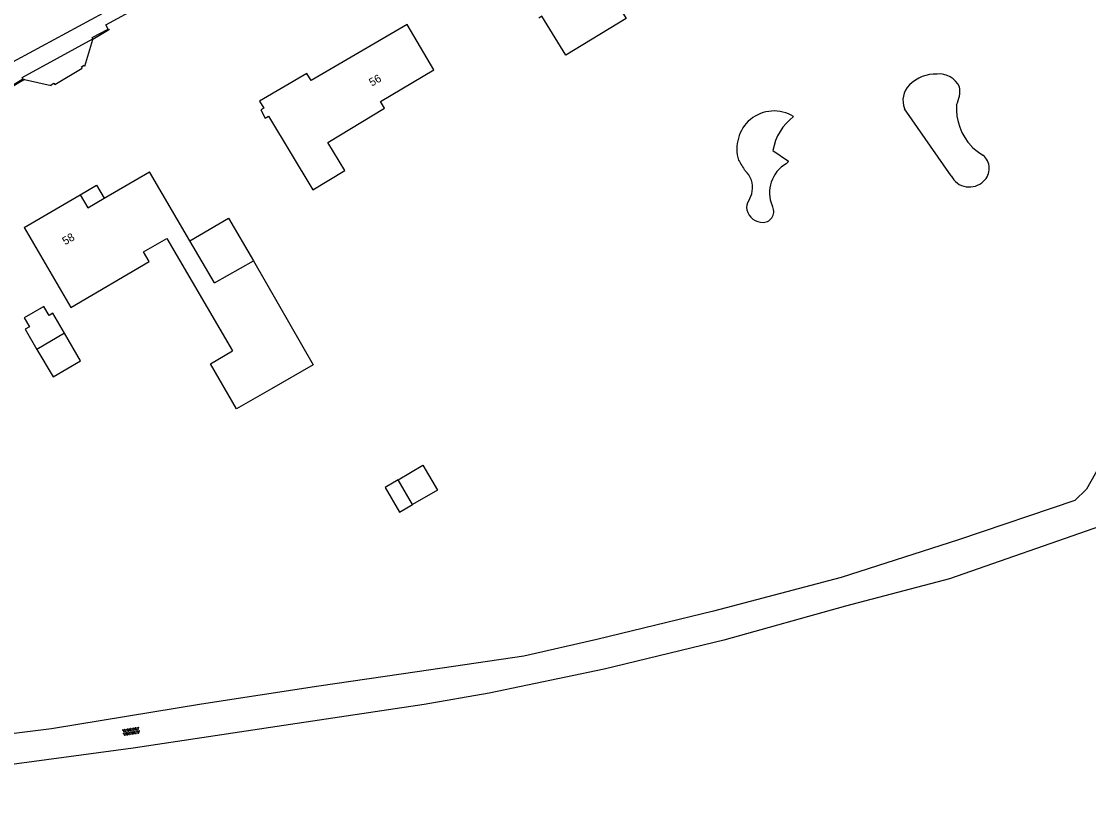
# Model space of a CAD drawing. Extents: x 135999 to 138000, y 396000 to 398501.
# Drawn here: x 136414.4 to 136547.8, y 397514.6 to 397614 of the extents above; entities that cross this region are included whole.
import ezdxf

# ---------------------------------------------------------------- set-up
doc = ezdxf.new("R2010")
doc.units = 0
for name, color, linetype in [('gg-afsc-hekwerk', 7, 'Continuous'), ('gg-anno-huisnummerreeks BGT', 7, 'Continuous'), ('gg-bbg-gedigitaliseerde bebouwing', 7, 'Continuous'), ('gg-bbg-gedigitaliseerde bijgebouw', 7, 'Continuous'), ('gg-bbg-hoofdgebouw', 7, 'Continuous'), ('gg-bbg-luifel en loopbrug', 7, 'Continuous'), ('gg-knt-onverhard', 7, 'Continuous'), ('gg-knt-verharding', 7, 'Continuous'), ('gg-kntw-bovenkant insteek waterloop', 7, 'Continuous'), ('gt-symb-overige verharding', 7, 'Continuous')]:
    doc.layers.add(name, color=color, linetype=linetype)

# ---------------------------------------------------------------- blocks, each defined once
blk = doc.blocks.new('gt0-OVH')
at = {"layer": 'gt-symb-overige verharding'}
for points in [[(-0.97, 0.3), (-0.97, 0.31), (-0.96, 0.32), (-0.97, 0.33), (-0.97, 0.34), (-0.98, 0.35), (-0.99, 0.35), (-1, 0.36), (-1.01, 0.35), (-1.02, 0.35), (-1.03, 0.34), (-1.03, 0.33), (-1.04, 0.32), (-1.03, 0.31), (-1.03, 0.3), (-1.02, 0.29), (-1.01, 0.29), (-1, 0.28), (-0.99, 0.29), (-0.98, 0.29)], [(-0.87, 0.11), (-0.87, 0.12), (-0.86, 0.13), (-0.87, 0.14), (-0.87, 0.15), (-0.88, 0.16), (-0.89, 0.16), (-0.9, 0.16), (-0.91, 0.16), (-0.92, 0.16), (-0.93, 0.15), (-0.93, 0.14), (-0.94, 0.13), (-0.93, 0.12), (-0.93, 0.11), (-0.92, 0.1), (-0.91, 0.09), (-0.9, 0.09), (-0.89, 0.09), (-0.88, 0.1)], [(-0.77, 0.3), (-0.77, 0.31), (-0.76, 0.32), (-0.77, 0.33), (-0.77, 0.34), (-0.78, 0.35), (-0.79, 0.35), (-0.8, 0.36), (-0.81, 0.35), (-0.82, 0.35), (-0.83, 0.34), (-0.83, 0.33), (-0.84, 0.32), (-0.83, 0.31), (-0.83, 0.3), (-0.82, 0.29), (-0.81, 0.29), (-0.8, 0.28), (-0.79, 0.29), (-0.78, 0.29)], [(-0.67, 0.11), (-0.67, 0.12), (-0.66, 0.13), (-0.67, 0.14), (-0.67, 0.15), (-0.68, 0.16), (-0.69, 0.16), (-0.7, 0.16), (-0.71, 0.16), (-0.72, 0.16), (-0.73, 0.15), (-0.73, 0.14), (-0.74, 0.13), (-0.73, 0.12), (-0.73, 0.11), (-0.72, 0.1), (-0.71, 0.09), (-0.7, 0.09), (-0.69, 0.09), (-0.68, 0.1)], [(-0.57, 0.3), (-0.57, 0.31), (-0.56, 0.32), (-0.57, 0.33), (-0.57, 0.34), (-0.58, 0.35), (-0.59, 0.35), (-0.6, 0.36), (-0.61, 0.35), (-0.62, 0.35), (-0.63, 0.34), (-0.63, 0.33), (-0.64, 0.32), (-0.63, 0.31), (-0.63, 0.3), (-0.62, 0.29), (-0.61, 0.29), (-0.6, 0.28), (-0.59, 0.29), (-0.58, 0.29)], [(-0.47, 0.11), (-0.47, 0.12), (-0.46, 0.13), (-0.47, 0.14), (-0.47, 0.15), (-0.48, 0.16), (-0.49, 0.16), (-0.5, 0.16), (-0.51, 0.16), (-0.52, 0.16), (-0.53, 0.15), (-0.53, 0.14), (-0.54, 0.13), (-0.53, 0.12), (-0.53, 0.11), (-0.52, 0.1), (-0.51, 0.09), (-0.5, 0.09), (-0.49, 0.09), (-0.48, 0.1)], [(-0.37, 0.3), (-0.37, 0.31), (-0.36, 0.32), (-0.37, 0.33), (-0.37, 0.34), (-0.38, 0.35), (-0.39, 0.35), (-0.4, 0.36), (-0.41, 0.35), (-0.42, 0.35), (-0.43, 0.34), (-0.43, 0.33), (-0.44, 0.32), (-0.43, 0.31), (-0.43, 0.3), (-0.42, 0.29), (-0.41, 0.29), (-0.4, 0.28), (-0.39, 0.29), (-0.38, 0.29)], [(-0.27, 0.11), (-0.27, 0.12), (-0.26, 0.13), (-0.27, 0.14), (-0.27, 0.15), (-0.28, 0.16), (-0.29, 0.16), (-0.3, 0.16), (-0.31, 0.16), (-0.32, 0.16), (-0.33, 0.15), (-0.33, 0.14), (-0.34, 0.13), (-0.33, 0.12), (-0.33, 0.11), (-0.32, 0.1), (-0.31, 0.09), (-0.3, 0.09), (-0.29, 0.09), (-0.28, 0.1)], [(-0.17, 0.3), (-0.17, 0.31), (-0.16, 0.32), (-0.17, 0.33), (-0.17, 0.34), (-0.18, 0.35), (-0.19, 0.35), (-0.2, 0.36), (-0.21, 0.35), (-0.22, 0.35), (-0.23, 0.34), (-0.23, 0.33), (-0.24, 0.32), (-0.23, 0.31), (-0.23, 0.3), (-0.22, 0.29), (-0.21, 0.29), (-0.2, 0.28), (-0.19, 0.29), (-0.18, 0.29)], [(-0.07, 0.11), (-0.07, 0.12), (-0.06, 0.13), (-0.07, 0.14), (-0.07, 0.15), (-0.08, 0.16), (-0.09, 0.16), (-0.1, 0.16), (-0.11, 0.16), (-0.12, 0.16), (-0.13, 0.15), (-0.13, 0.14), (-0.14, 0.13), (-0.13, 0.12), (-0.13, 0.11), (-0.12, 0.1), (-0.11, 0.09), (-0.1, 0.09), (-0.09, 0.09), (-0.08, 0.1)], [(0.03, 0.3), (0.03, 0.31), (0.04, 0.32), (0.03, 0.33), (0.03, 0.34), (0.02, 0.35), (0.01, 0.35), (0, 0.36), (-0.01, 0.35), (-0.02, 0.35), (-0.03, 0.34), (-0.03, 0.33), (-0.04, 0.32), (-0.03, 0.31), (-0.03, 0.3), (-0.02, 0.29), (-0.01, 0.29), (0, 0.28), (0.01, 0.29), (0.02, 0.29)], [(0.13, 0.11), (0.13, 0.12), (0.14, 0.13), (0.13, 0.14), (0.13, 0.15), (0.12, 0.16), (0.11, 0.16), (0.1, 0.16), (0.09, 0.16), (0.08, 0.16), (0.07, 0.15), (0.07, 0.14), (0.06, 0.13), (0.07, 0.12), (0.07, 0.11), (0.08, 0.1), (0.09, 0.09), (0.1, 0.09), (0.11, 0.09), (0.12, 0.1)], [(0.23, 0.3), (0.23, 0.31), (0.24, 0.32), (0.23, 0.33), (0.23, 0.34), (0.22, 0.35), (0.21, 0.35), (0.2, 0.36), (0.19, 0.35), (0.18, 0.35), (0.17, 0.34), (0.17, 0.33), (0.16, 0.32), (0.17, 0.31), (0.17, 0.3), (0.18, 0.29), (0.19, 0.29), (0.2, 0.28), (0.21, 0.29), (0.22, 0.29)], [(0.33, 0.11), (0.33, 0.12), (0.34, 0.13), (0.33, 0.14), (0.33, 0.15), (0.32, 0.16), (0.31, 0.16), (0.3, 0.16), (0.29, 0.16), (0.28, 0.16), (0.27, 0.15), (0.27, 0.14), (0.26, 0.13), (0.27, 0.12), (0.27, 0.11), (0.28, 0.1), (0.29, 0.09), (0.3, 0.09), (0.31, 0.09), (0.32, 0.1)], [(0.43, 0.3), (0.43, 0.31), (0.44, 0.32), (0.43, 0.33), (0.43, 0.34), (0.42, 0.35), (0.41, 0.35), (0.4, 0.36), (0.39, 0.35), (0.38, 0.35), (0.37, 0.34), (0.37, 0.33), (0.36, 0.32), (0.37, 0.31), (0.37, 0.3), (0.38, 0.29), (0.39, 0.29), (0.4, 0.28), (0.41, 0.29), (0.42, 0.29)], [(0.53, 0.11), (0.53, 0.12), (0.54, 0.13), (0.53, 0.14), (0.53, 0.15), (0.52, 0.16), (0.51, 0.16), (0.5, 0.16), (0.49, 0.16), (0.48, 0.16), (0.47, 0.15), (0.47, 0.14), (0.46, 0.13), (0.47, 0.12), (0.47, 0.11), (0.48, 0.1), (0.49, 0.09), (0.5, 0.09), (0.51, 0.09), (0.52, 0.1)], [(0.63, 0.3), (0.63, 0.31), (0.64, 0.32), (0.63, 0.33), (0.63, 0.34), (0.62, 0.35), (0.61, 0.35), (0.6, 0.36), (0.59, 0.35), (0.58, 0.35), (0.57, 0.34), (0.57, 0.33), (0.56, 0.32), (0.57, 0.31), (0.57, 0.3), (0.58, 0.29), (0.59, 0.29), (0.6, 0.28), (0.61, 0.29), (0.62, 0.29)], [(0.73, 0.11), (0.73, 0.12), (0.74, 0.13), (0.73, 0.14), (0.73, 0.15), (0.72, 0.16), (0.71, 0.16), (0.7, 0.16), (0.69, 0.16), (0.68, 0.16), (0.67, 0.15), (0.67, 0.14), (0.66, 0.13), (0.67, 0.12), (0.67, 0.11), (0.68, 0.1), (0.69, 0.09), (0.7, 0.09), (0.71, 0.09), (0.72, 0.1)], [(0.83, 0.3), (0.83, 0.31), (0.84, 0.32), (0.83, 0.33), (0.83, 0.34), (0.82, 0.35), (0.81, 0.35), (0.8, 0.36), (0.79, 0.35), (0.78, 0.35), (0.77, 0.34), (0.77, 0.33), (0.76, 0.32), (0.77, 0.31), (0.77, 0.3), (0.78, 0.29), (0.79, 0.29), (0.8, 0.28), (0.81, 0.29), (0.82, 0.29)], [(0.93, 0.11), (0.93, 0.12), (0.94, 0.13), (0.93, 0.14), (0.93, 0.15), (0.92, 0.16), (0.91, 0.16), (0.9, 0.16), (0.89, 0.16), (0.88, 0.16), (0.87, 0.15), (0.87, 0.14), (0.86, 0.13), (0.87, 0.12), (0.87, 0.11), (0.88, 0.1), (0.89, 0.09), (0.9, 0.09), (0.91, 0.09), (0.92, 0.1)], [(1.03, 0.3), (1.03, 0.31), (1.04, 0.32), (1.03, 0.33), (1.03, 0.34), (1.02, 0.35), (1.01, 0.35), (1, 0.36), (0.99, 0.35), (0.98, 0.35), (0.97, 0.34), (0.97, 0.33), (0.96, 0.32), (0.97, 0.31), (0.97, 0.3), (0.98, 0.29), (0.99, 0.29), (1, 0.28), (1.01, 0.29), (1.02, 0.29)], [(-0.97, -0.14), (-0.97, -0.13), (-0.96, -0.12), (-0.97, -0.11), (-0.97, -0.1), (-0.98, -0.09), (-0.99, -0.09), (-1, -0.08), (-1.01, -0.09), (-1.02, -0.09), (-1.03, -0.1), (-1.03, -0.11), (-1.04, -0.12), (-1.03, -0.13), (-1.03, -0.14), (-1.02, -0.15), (-1.01, -0.15), (-1, -0.16), (-0.99, -0.15), (-0.98, -0.15)], [(-0.87, -0.33), (-0.87, -0.32), (-0.86, -0.31), (-0.87, -0.3), (-0.87, -0.29), (-0.88, -0.28), (-0.89, -0.28), (-0.9, -0.28), (-0.91, -0.28), (-0.92, -0.28), (-0.93, -0.29), (-0.93, -0.3), (-0.94, -0.31), (-0.93, -0.32), (-0.93, -0.33), (-0.92, -0.34), (-0.91, -0.35), (-0.9, -0.35), (-0.89, -0.35), (-0.88, -0.34)], [(-0.77, -0.14), (-0.77, -0.13), (-0.76, -0.12), (-0.77, -0.11), (-0.77, -0.1), (-0.78, -0.09), (-0.79, -0.09), (-0.8, -0.08), (-0.81, -0.09), (-0.82, -0.09), (-0.83, -0.1), (-0.83, -0.11), (-0.84, -0.12), (-0.83, -0.13), (-0.83, -0.14), (-0.82, -0.15), (-0.81, -0.15), (-0.8, -0.16), (-0.79, -0.15), (-0.78, -0.15)], [(-0.67, -0.33), (-0.67, -0.32), (-0.66, -0.31), (-0.67, -0.3), (-0.67, -0.29), (-0.68, -0.28), (-0.69, -0.28), (-0.7, -0.28), (-0.71, -0.28), (-0.72, -0.28), (-0.73, -0.29), (-0.73, -0.3), (-0.74, -0.31), (-0.73, -0.32), (-0.73, -0.33), (-0.72, -0.34), (-0.71, -0.35), (-0.7, -0.35), (-0.69, -0.35), (-0.68, -0.34)], [(-0.57, -0.14), (-0.57, -0.13), (-0.56, -0.12), (-0.57, -0.11), (-0.57, -0.1), (-0.58, -0.09), (-0.59, -0.09), (-0.6, -0.08), (-0.61, -0.09), (-0.62, -0.09), (-0.63, -0.1), (-0.63, -0.11), (-0.64, -0.12), (-0.63, -0.13), (-0.63, -0.14), (-0.62, -0.15), (-0.61, -0.15), (-0.6, -0.16), (-0.59, -0.15), (-0.58, -0.15)], [(-0.47, -0.33), (-0.47, -0.32), (-0.46, -0.31), (-0.47, -0.3), (-0.47, -0.29), (-0.48, -0.28), (-0.49, -0.28), (-0.5, -0.28), (-0.51, -0.28), (-0.52, -0.28), (-0.53, -0.29), (-0.53, -0.3), (-0.54, -0.31), (-0.53, -0.32), (-0.53, -0.33), (-0.52, -0.34), (-0.51, -0.35), (-0.5, -0.35), (-0.49, -0.35), (-0.48, -0.34)], [(-0.37, -0.14), (-0.37, -0.13), (-0.36, -0.12), (-0.37, -0.11), (-0.37, -0.1), (-0.38, -0.09), (-0.39, -0.09), (-0.4, -0.08), (-0.41, -0.09), (-0.42, -0.09), (-0.43, -0.1), (-0.43, -0.11), (-0.44, -0.12), (-0.43, -0.13), (-0.43, -0.14), (-0.42, -0.15), (-0.41, -0.15), (-0.4, -0.16), (-0.39, -0.15), (-0.38, -0.15)], [(-0.27, -0.33), (-0.27, -0.32), (-0.26, -0.31), (-0.27, -0.3), (-0.27, -0.29), (-0.28, -0.28), (-0.29, -0.28), (-0.3, -0.28), (-0.31, -0.28), (-0.32, -0.28), (-0.33, -0.29), (-0.33, -0.3), (-0.34, -0.31), (-0.33, -0.32), (-0.33, -0.33), (-0.32, -0.34), (-0.31, -0.35), (-0.3, -0.35), (-0.29, -0.35), (-0.28, -0.34)], [(-0.17, -0.14), (-0.17, -0.13), (-0.16, -0.12), (-0.17, -0.11), (-0.17, -0.1), (-0.18, -0.09), (-0.19, -0.09), (-0.2, -0.08), (-0.21, -0.09), (-0.22, -0.09), (-0.23, -0.1), (-0.23, -0.11), (-0.24, -0.12), (-0.23, -0.13), (-0.23, -0.14), (-0.22, -0.15), (-0.21, -0.15), (-0.2, -0.16), (-0.19, -0.15), (-0.18, -0.15)], [(-0.07, -0.33), (-0.07, -0.32), (-0.06, -0.31), (-0.07, -0.3), (-0.07, -0.29), (-0.08, -0.28), (-0.09, -0.28), (-0.1, -0.28), (-0.11, -0.28), (-0.12, -0.28), (-0.13, -0.29), (-0.13, -0.3), (-0.14, -0.31), (-0.13, -0.32), (-0.13, -0.33), (-0.12, -0.34), (-0.11, -0.35), (-0.1, -0.35), (-0.09, -0.35), (-0.08, -0.34)], [(0.03, -0.14), (0.03, -0.13), (0.04, -0.12), (0.03, -0.11), (0.03, -0.1), (0.02, -0.09), (0.01, -0.09), (0, -0.08), (-0.01, -0.09), (-0.02, -0.09), (-0.03, -0.1), (-0.03, -0.11), (-0.04, -0.12), (-0.03, -0.13), (-0.03, -0.14), (-0.02, -0.15), (-0.01, -0.15), (0, -0.16), (0.01, -0.15), (0.02, -0.15)], [(0.13, -0.33), (0.13, -0.32), (0.14, -0.31), (0.13, -0.3), (0.13, -0.29), (0.12, -0.28), (0.11, -0.28), (0.1, -0.28), (0.09, -0.28), (0.08, -0.28), (0.07, -0.29), (0.07, -0.3), (0.06, -0.31), (0.07, -0.32), (0.07, -0.33), (0.08, -0.34), (0.09, -0.35), (0.1, -0.35), (0.11, -0.35), (0.12, -0.34)], [(0.23, -0.14), (0.23, -0.13), (0.24, -0.12), (0.23, -0.11), (0.23, -0.1), (0.22, -0.09), (0.21, -0.09), (0.2, -0.08), (0.19, -0.09), (0.18, -0.09), (0.17, -0.1), (0.17, -0.11), (0.16, -0.12), (0.17, -0.13), (0.17, -0.14), (0.18, -0.15), (0.19, -0.15), (0.2, -0.16), (0.21, -0.15), (0.22, -0.15)], [(0.33, -0.33), (0.33, -0.32), (0.34, -0.31), (0.33, -0.3), (0.33, -0.29), (0.32, -0.28), (0.31, -0.28), (0.3, -0.28), (0.29, -0.28), (0.28, -0.28), (0.27, -0.29), (0.27, -0.3), (0.26, -0.31), (0.27, -0.32), (0.27, -0.33), (0.28, -0.34), (0.29, -0.35), (0.3, -0.35), (0.31, -0.35), (0.32, -0.34)], [(0.43, -0.14), (0.43, -0.13), (0.44, -0.12), (0.43, -0.11), (0.43, -0.1), (0.42, -0.09), (0.41, -0.09), (0.4, -0.08), (0.39, -0.09), (0.38, -0.09), (0.37, -0.1), (0.37, -0.11), (0.36, -0.12), (0.37, -0.13), (0.37, -0.14), (0.38, -0.15), (0.39, -0.15), (0.4, -0.16), (0.41, -0.15), (0.42, -0.15)], [(0.53, -0.33), (0.53, -0.32), (0.54, -0.31), (0.53, -0.3), (0.53, -0.29), (0.52, -0.28), (0.51, -0.28), (0.5, -0.28), (0.49, -0.28), (0.48, -0.28), (0.47, -0.29), (0.47, -0.3), (0.46, -0.31), (0.47, -0.32), (0.47, -0.33), (0.48, -0.34), (0.49, -0.35), (0.5, -0.35), (0.51, -0.35), (0.52, -0.34)], [(0.63, -0.14), (0.63, -0.13), (0.64, -0.12), (0.63, -0.11), (0.63, -0.1), (0.62, -0.09), (0.61, -0.09), (0.6, -0.08), (0.59, -0.09), (0.58, -0.09), (0.57, -0.1), (0.57, -0.11), (0.56, -0.12), (0.57, -0.13), (0.57, -0.14), (0.58, -0.15), (0.59, -0.15), (0.6, -0.16), (0.61, -0.15), (0.62, -0.15)], [(0.73, -0.33), (0.73, -0.32), (0.74, -0.31), (0.73, -0.3), (0.73, -0.29), (0.72, -0.28), (0.71, -0.28), (0.7, -0.28), (0.69, -0.28), (0.68, -0.28), (0.67, -0.29), (0.67, -0.3), (0.66, -0.31), (0.67, -0.32), (0.67, -0.33), (0.68, -0.34), (0.69, -0.35), (0.7, -0.35), (0.71, -0.35), (0.72, -0.34)], [(0.83, -0.14), (0.83, -0.13), (0.84, -0.12), (0.83, -0.11), (0.83, -0.1), (0.82, -0.09), (0.81, -0.09), (0.8, -0.08), (0.79, -0.09), (0.78, -0.09), (0.77, -0.1), (0.77, -0.11), (0.76, -0.12), (0.77, -0.13), (0.77, -0.14), (0.78, -0.15), (0.79, -0.15), (0.8, -0.16), (0.81, -0.15), (0.82, -0.15)], [(0.93, -0.33), (0.93, -0.32), (0.94, -0.31), (0.93, -0.3), (0.93, -0.29), (0.92, -0.28), (0.91, -0.28), (0.9, -0.28), (0.89, -0.28), (0.88, -0.28), (0.87, -0.29), (0.87, -0.3), (0.86, -0.31), (0.87, -0.32), (0.87, -0.33), (0.88, -0.34), (0.89, -0.35), (0.9, -0.35), (0.91, -0.35), (0.92, -0.34)], [(1.03, -0.14), (1.03, -0.13), (1.04, -0.12), (1.03, -0.11), (1.03, -0.1), (1.02, -0.09), (1.01, -0.09), (1, -0.08), (0.99, -0.09), (0.98, -0.09), (0.97, -0.1), (0.97, -0.11), (0.96, -0.12), (0.97, -0.13), (0.97, -0.14), (0.98, -0.15), (0.99, -0.15), (1, -0.16), (1.01, -0.15), (1.02, -0.15)]]:
    blk.add_lwpolyline(points, close=True, dxfattribs=at)

msp = doc.modelspace()

# ---------------------------------------------------------------- linework, layer by layer
at = {"layer": 'gg-afsc-hekwerk'}
for p, q in [((136425.44, 397612.99), (136423.33, 397611.76)), ((136423.33, 397611.76), (136423.35, 397611.81)), ((136414.81, 397606.76), (136376.12, 397584.09)), ((136414.59, 397606.81), (136414.81, 397606.76))]:
    msp.add_line(p, q, dxfattribs=at)
for points in [[(136414.81, 397606.76), (136418.15, 397605.99), (136418.13, 397606.09), (136418.46, 397606.28), (136418.58, 397606.14), (136421.99, 397608.18), (136421.93, 397608.34), (136422.26, 397608.52), (136422.35, 397608.4), (136423.33, 397611.76)], [(136621.41, 397588.85), (136621.41, 397588.86), (136620.92, 397588.03), (136585.79, 397571.67), (136553.18, 397557.43), (136549.48, 397559.1), (136547.48, 397555.56), (136546.05, 397554.14), (136531.52, 397549.24), (136516.85, 397544.53), (136500.88, 397540.31), (136486.31, 397536.77), (136477.19, 397534.69), (136463.85, 397532.73), (136451.57, 397530.92), (136436.93, 397528.7), (136418.19, 397525.62), (136399.19, 397523.23)], [(136621.41, 397588.85), (136621.41, 397588.86), (136620.92, 397588.03), (136585.79, 397571.67), (136553.18, 397557.43), (136549.48, 397559.1), (136547.48, 397555.56), (136546.05, 397554.14), (136531.52, 397549.24), (136516.85, 397544.53), (136500.88, 397540.31), (136486.31, 397536.77), (136477.19, 397534.69), (136463.85, 397532.73), (136451.57, 397530.92), (136436.93, 397528.7), (136418.19, 397525.62), (136399.19, 397523.23)]]:
    msp.add_lwpolyline(points, dxfattribs=at)
at = {"layer": 'gg-bbg-gedigitaliseerde bebouwing'}
for p, q in [((136444.88, 397601.92), (136445.3, 397602.16)), ((136445.3, 397602.16), (136450.84, 397592.96)), ((136435.45, 397586.59), (136430.4, 397595.21)), ((136432.57, 397586.88), (136440.81, 397572.82)), ((136438.55, 397581.32), (136435.45, 397586.59)), ((136438.55, 397581.32), (136443.43, 397584.1))]:
    msp.add_line(p, q, dxfattribs=at)
for points in [[(136494.12, 397627.94), (136498.43, 397620.74), (136489.42, 397615.26), (136489.97, 397614.35), (136482.43, 397609.77), (136479.46, 397614.66), (136479.05, 397614.4)], [(136459.79, 397603.16), (136459.3, 397603.98), (136465.93, 397607.95), (136462.6, 397613.62)], [(136450.84, 397592.96), (136454.83, 397595.36), (136452.7, 397598.88), (136459.79, 397603.16)], [(136414.77, 397588.26), (136420.61, 397578.27), (136430.38, 397583.99), (136429.67, 397585.19), (136432.57, 397586.88)], [(136443.43, 397584.1), (136450.87, 397571.07), (136445.66, 397568.09)], [(136445.66, 397568.09), (136441.3, 397565.59), (136438.05, 397571.23), (136440.81, 397572.82)]]:
    msp.add_lwpolyline(points, dxfattribs=at)
at = {"layer": 'gg-bbg-gedigitaliseerde bijgebouw'}
for p, q in [((136419.79, 397575.03), (136416.36, 397573.01)), ((136463.3, 397553.62), (136461.48, 397556.72))]:
    msp.add_line(p, q, dxfattribs=at)
for points in [[(136419.79, 397575.03), (136418.32, 397577.54), (136417.87, 397577.27), (136417.21, 397578.39), (136414.77, 397576.96), (136415.42, 397575.84), (136414.89, 397575.53), (136416.36, 397573.01)], [(136461.48, 397556.72), (136464.58, 397558.54), (136466.4, 397555.44), (136463.3, 397553.62)]]:
    msp.add_lwpolyline(points, dxfattribs=at)
at = {"layer": 'gg-bbg-hoofdgebouw'}
for p, q in [((136424.76, 397591.91), (136430.4, 397595.21)), ((136414.77, 397588.26), (136421.77, 397592.33))]:
    msp.add_line(p, q, dxfattribs=at)
for points in [[(136462.6, 397613.62), (136450.6, 397606.63), (136450.09, 397607.5), (136444.16, 397604.05), (136444.69, 397603.17), (136444.31, 397602.96), (136444.88, 397601.92)], [(136421.77, 397592.33), (136422.72, 397590.71), (136424.76, 397591.91)]]:
    msp.add_lwpolyline(points, dxfattribs=at)
at = {"layer": 'gg-bbg-luifel en loopbrug'}
for points in [[(136421.77, 397592.33), (136423.81, 397593.53), (136424.76, 397591.91)], [(136435.45, 397586.59), (136440.31, 397589.43), (136443.43, 397584.1)], [(136416.36, 397573.01), (136418.37, 397569.58), (136421.8, 397571.59), (136419.79, 397575.03)], [(136461.48, 397556.72), (136459.85, 397555.77), (136461.67, 397552.66), (136463.3, 397553.62)]]:
    msp.add_lwpolyline(points, dxfattribs=at)
at = {"layer": 'gg-knt-onverhard'}
msp.add_lwpolyline([(136639.25, 397592.88), (136622.55, 397584.43), (136599.63, 397573.26), (136579.98, 397563.99), (136564.37, 397556.96), (136549.26, 397550.93), (136530.39, 397544.36), (136517.4, 397540.95), (136502.17, 397536.7), (136487.24, 397533.05), (136472.84, 397530.05), (136464.73, 397528.63), (136447.21, 397526.03), (136428.36, 397523.18), (136405.13, 397520.07), (136381.86, 397517.11), (136373.14, 397515.77), (136364.18, 397515.21), (136350.89, 397515.12), (136338, 397514.73), (136334.6, 397514.07)], dxfattribs=at)
at = {"layer": 'gg-knt-verharding'}
for points in [[(136423.35, 397611.81), (136423.24, 397611.99), (136425.24, 397613.05), (136424.96, 397613.59), (136443.29, 397623.58), (136486.57, 397648.9), (136508.09, 397661.5), (136508.13, 397661.42)], [(136454.41, 397631.76), (136442.38, 397624.71), (136424.64, 397615.04), (136407.64, 397605.89), (136385.8, 397594.1), (136375.91, 397588.77), (136371.17, 397586.09), (136359.16, 397578.94), (136356.4, 397577.24), (136355.96, 397576.96), (136353.05, 397575.22), (136350.19, 397573.46), (136347.62, 397571.75), (136345.87, 397570.5), (136342.75, 397568.12), (136339.37, 397565.46), (136337.59, 397564.11), (136335.32, 397562.48), (136333.1, 397561.03), (136330.86, 397559.61), (136325.73, 397556.55), (136319.82, 397553.1)], [(136414.59, 397606.81), (136414.49, 397606.99), (136423.35, 397611.81)], [(136368.53, 397582.68), (136374.37, 397586.1), (136375.62, 397583.86), (136400.99, 397598.79), (136412.08, 397605.29), (136414.59, 397606.81)]]:
    msp.add_lwpolyline(points, dxfattribs=at)
at = {"layer": 'gg-kntw-bovenkant insteek waterloop'}
for p, q in [((136530.6, 397594.71), (136524.77, 397603.1)), ((136508.32, 397597.87), (136510.27, 397596.56))]:
    msp.add_line(p, q, dxfattribs=at)
for centre, radius, start, end in [((136528.67, 397602.79), 4.64, 88.0152, 135.2041), ((136529.09, 397604.62), 2.82, 25.5761, 95.3392), ((136527.26, 397604.14), 2.7, 134.4404, 202.635), ((136527.75, 397605.34), 3.92, 333.3175, 7.3889), ((136508.46, 397598.12), 4.69, 58.5411, 129.1166), ((136538.22, 397603.16), 6.98, 176.5483, 223.4585), ((136508.7, 397598.07), 4.89, 130.9332, 196.8565), ((136515.06, 397596.68), 6.85, 127.3191, 169.9483), ((136538.99, 397604.68), 8.61, 227.2698, 239.0164), ((136533.22, 397595.64), 2.13, 311.4488, 50.9778), ((136514.7, 397602.42), 12.13, 208.3725, 215.5985), ((136512.09, 397592.59), 4.2, 120.1566, 202.4753), ((136509.48, 397596.96), 0.89, 304.3461, 333.4508), ((136502.97, 397593.25), 2.81, 350.2251, 48.4222), ((136532.86, 397595.84), 2.53, 206.6235, 314.4887), ((136502.66, 397593.25), 3.11, 328.0343, 351.2079), ((136506.55, 397590.75), 1.52, 145.6198, 191.8169), ((136507.08, 397590.96), 2.08, 194.4447, 271.0232), ((136507.07, 397590.24), 1.36, 271.8739, 33.3997)]:
    msp.add_arc(centre, radius, start, end, dxfattribs=at)

# ---------------------------------------------------------------- block references
at = {"layer": 'gt-symb-overige verharding', "rotation": 8.802804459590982}
msp.add_blockref('gt0-OVH', (136428.12, 397525.28), dxfattribs=at)

# ---------------------------------------------------------------- texts
at = {"layer": 'gg-anno-huisnummerreeks BGT'}
for s, p in [('56', (136458.21, 397605.85)), ('58', (136419.88, 397586.02))]:
    msp.add_text(s, height=1, rotation=30.2, dxfattribs=at).set_placement(p)

doc.saveas('drawing.dxf')
